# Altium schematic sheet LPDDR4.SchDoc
size D; SheetNumber: 9; SheetTotal: 9
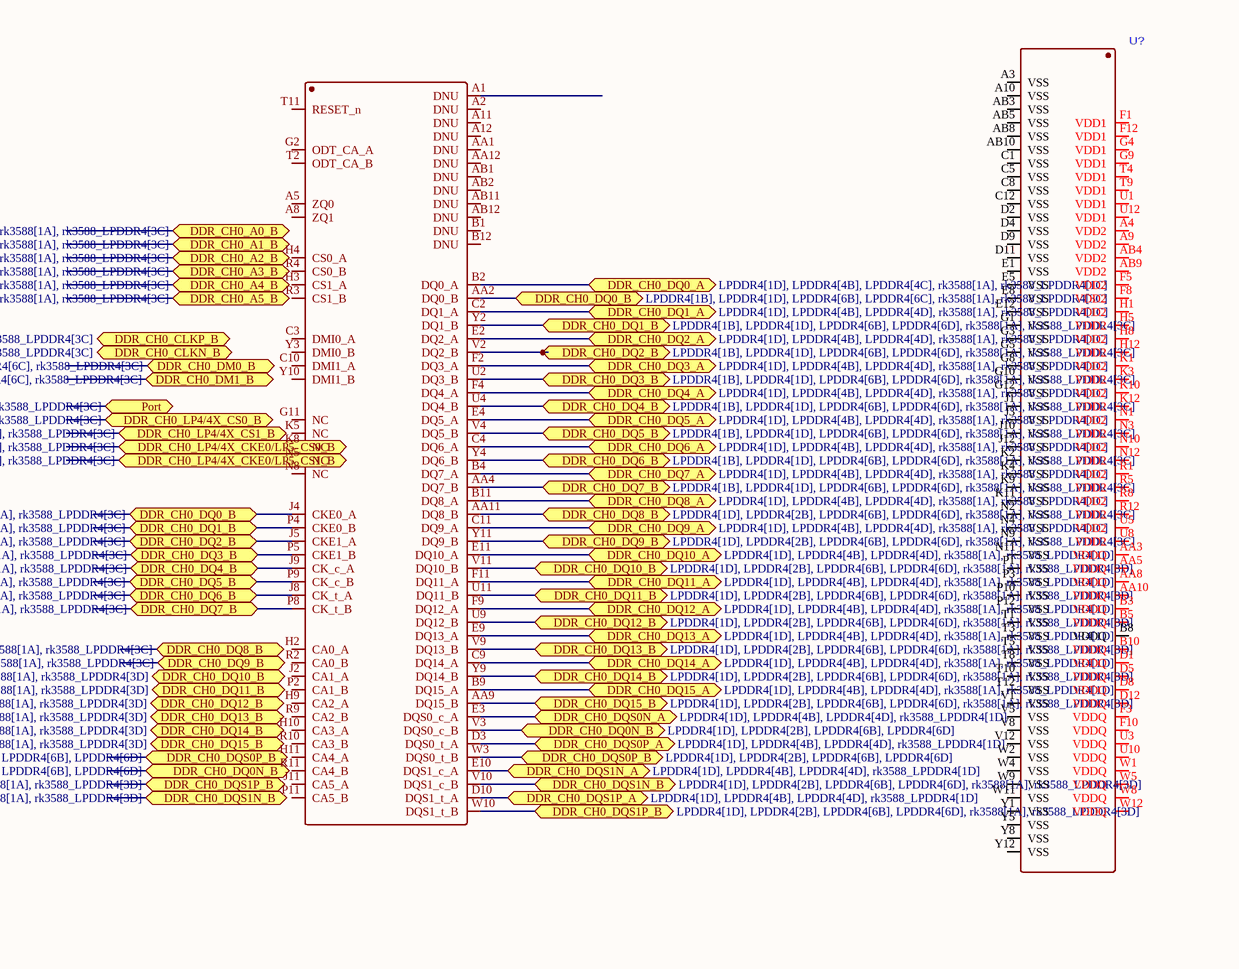
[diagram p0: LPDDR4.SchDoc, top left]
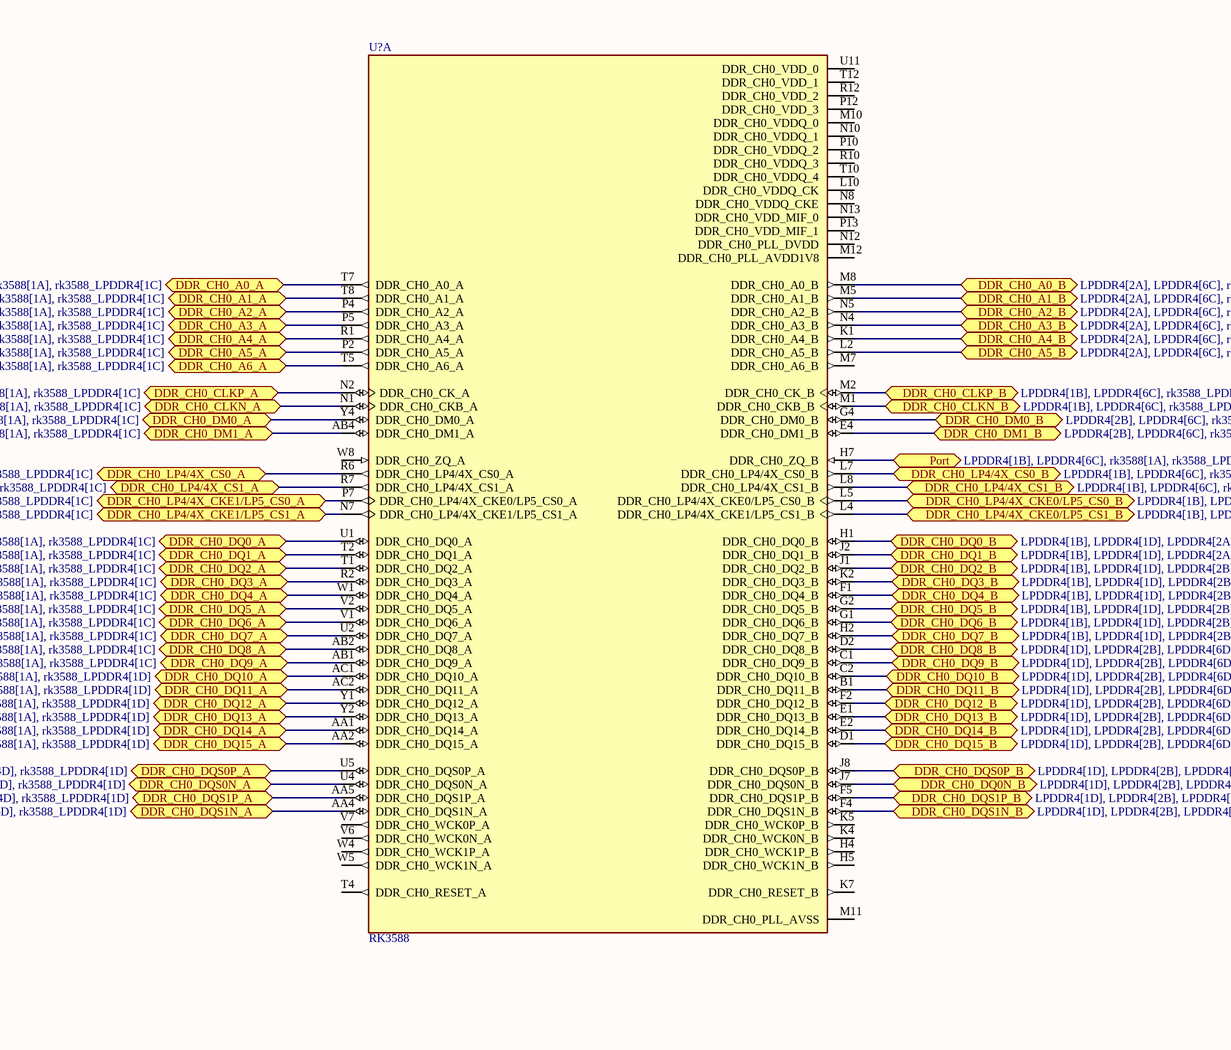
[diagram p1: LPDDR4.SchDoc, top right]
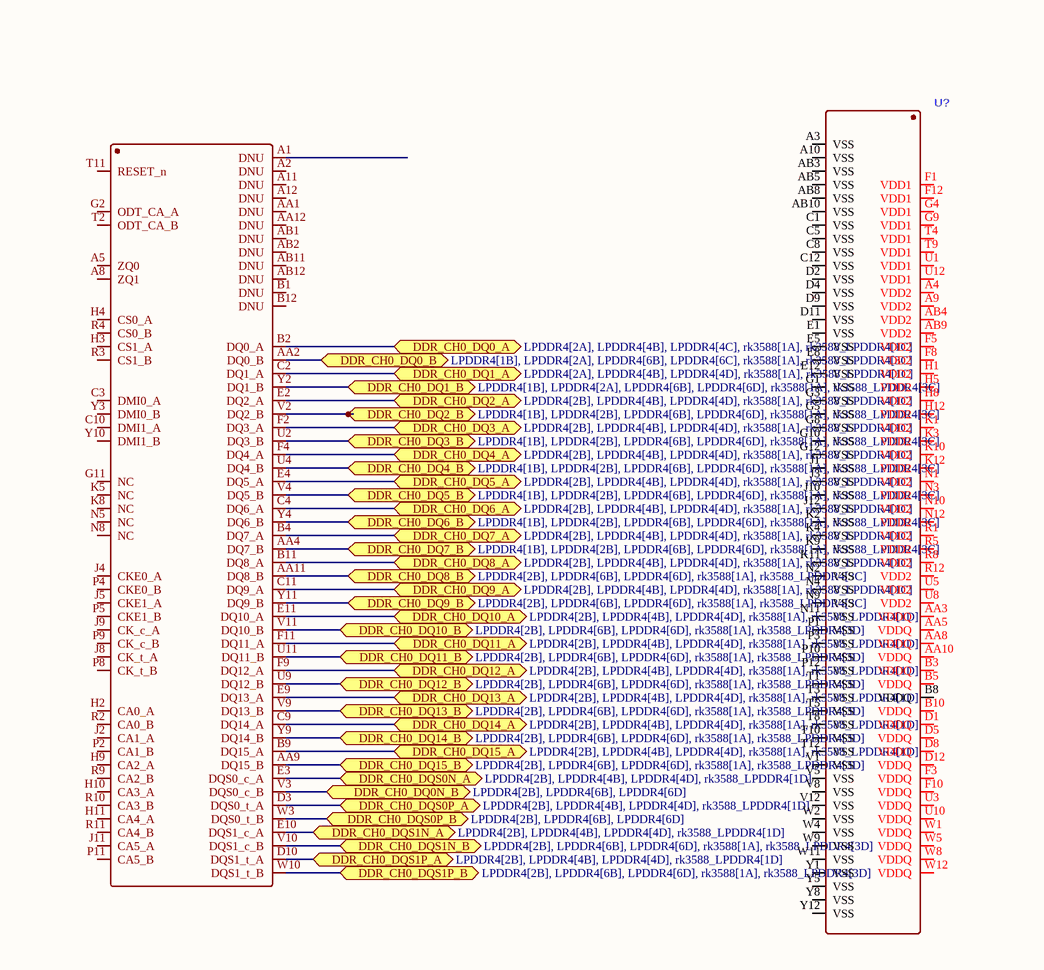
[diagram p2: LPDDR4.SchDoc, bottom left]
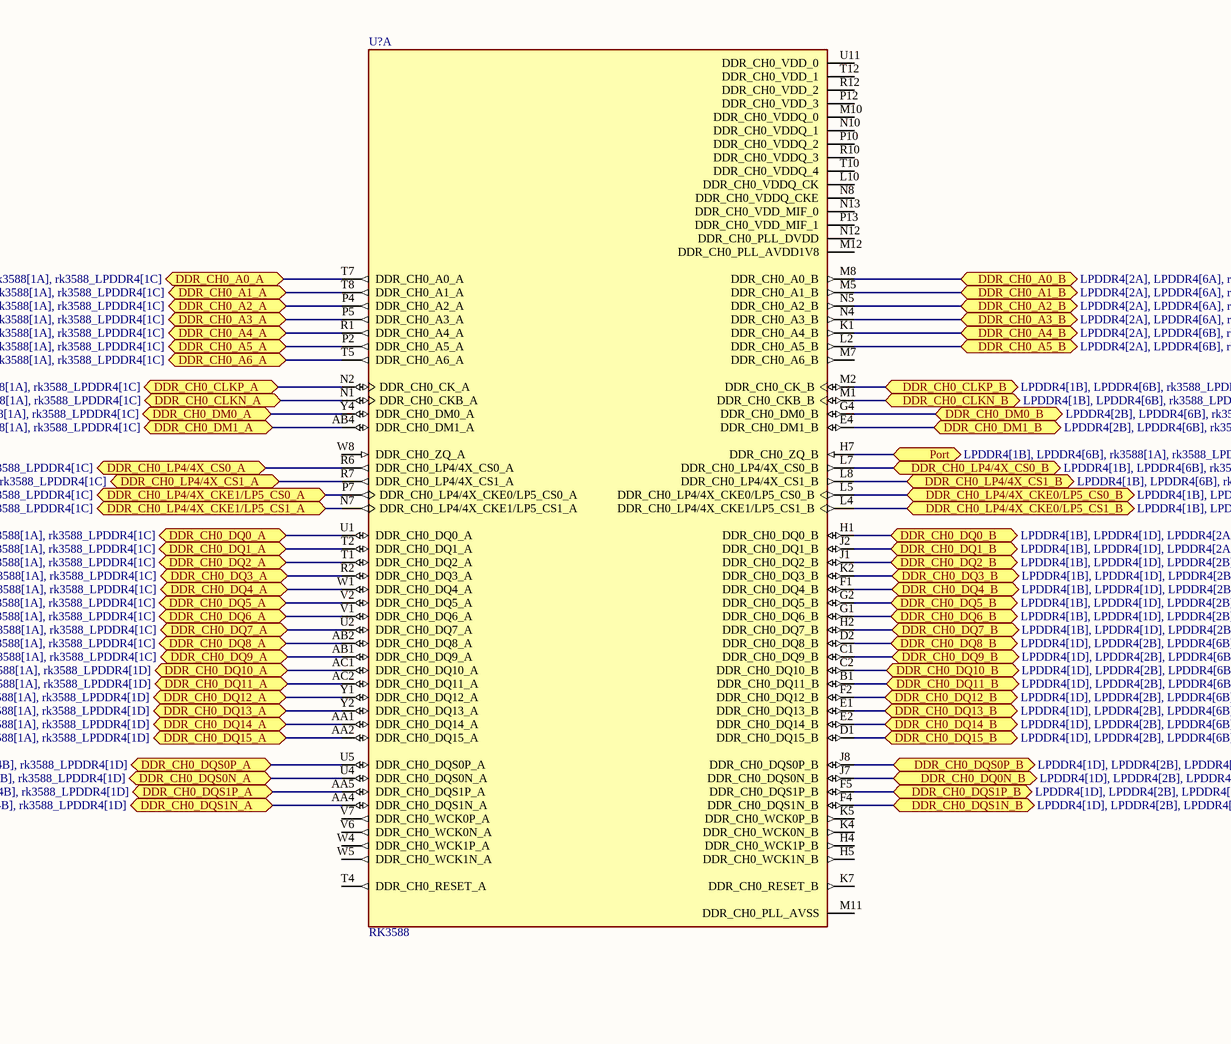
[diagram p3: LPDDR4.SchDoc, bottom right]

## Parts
(Parts that share a designator on the sheet are numbered #1, #2 ... from top to bottom, then left to right.)
U?#1  (no value)  [WFBGA-200_L14.5-W10.0-BL_MT53D512M32D2DS]
U?#2  RK3588  [BGA1088C65P34X34_2300X2300X204N]  (part A of 30)
U?#3  RK3588  [BGA1088C65P34X34_2300X2300X204N]  (part A of 30)
U?#4  (no value)  [WFBGA-200_L14.5-W10.0-BL_MT53D512M32D2DS]

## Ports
DDR_CH0_A0_A (bidir, see LPDDR4[4A], rk3588[1A], rk3588_LPDDR4[1C]), DDR_CH0_A0_A (bidir, see LPDDR4[4C], rk3588[1A], rk3588_LPDDR4[1C]), DDR_CH0_A0_B (bidir, see LPDDR4[2A], LPDDR4[6A], rk3588[1A], rk3588_LPDDR4[3C]), DDR_CH0_A0_B (bidir, see LPDDR4[2A], LPDDR4[6C], rk3588[1A], rk3588_LPDDR4[3C]), DDR_CH0_A0_B (bidir, see LPDDR4[6A], LPDDR4[6C], rk3588[1A], rk3588_LPDDR4[3C]), DDR_CH0_A1_A (bidir, see LPDDR4[4A], rk3588[1A], rk3588_LPDDR4[1C]), DDR_CH0_A1_A (bidir, see LPDDR4[4C], rk3588[1A], rk3588_LPDDR4[1C]), DDR_CH0_A1_B (bidir, see LPDDR4[2A], LPDDR4[6A], rk3588[1A], rk3588_LPDDR4[3C]), DDR_CH0_A1_B (bidir, see LPDDR4[2A], LPDDR4[6C], rk3588[1A], rk3588_LPDDR4[3C]), DDR_CH0_A1_B (bidir, see LPDDR4[6A], LPDDR4[6C], rk3588[1A], rk3588_LPDDR4[3C]), DDR_CH0_A2_A (bidir, see LPDDR4[4A], rk3588[1A], rk3588_LPDDR4[1C]), DDR_CH0_A2_A (bidir, see LPDDR4[4C], rk3588[1A], rk3588_LPDDR4[1C]), DDR_CH0_A2_B (bidir, see LPDDR4[2A], LPDDR4[6A], rk3588[1A], rk3588_LPDDR4[3C]), DDR_CH0_A2_B (bidir, see LPDDR4[2A], LPDDR4[6C], rk3588[1A], rk3588_LPDDR4[3C]), DDR_CH0_A2_B (bidir, see LPDDR4[6A], LPDDR4[6C], rk3588[1A], rk3588_LPDDR4[3C]), DDR_CH0_A3_A (bidir, see LPDDR4[4A], rk3588[1A], rk3588_LPDDR4[1C]), DDR_CH0_A3_A (bidir, see LPDDR4[4C], rk3588[1A], rk3588_LPDDR4[1C]), DDR_CH0_A3_B (bidir, see LPDDR4[2A], LPDDR4[6A], rk3588[1A], rk3588_LPDDR4[3C]), DDR_CH0_A3_B (bidir, see LPDDR4[2A], LPDDR4[6C], rk3588[1A], rk3588_LPDDR4[3C]), DDR_CH0_A3_B (bidir, see LPDDR4[6A], LPDDR4[6C], rk3588[1A], rk3588_LPDDR4[3C]), DDR_CH0_A4_A (bidir, see LPDDR4[4B], rk3588[1A], rk3588_LPDDR4[1C]), DDR_CH0_A4_A (bidir, see LPDDR4[4C], rk3588[1A], rk3588_LPDDR4[1C]), DDR_CH0_A4_B (bidir, see LPDDR4[2A], LPDDR4[6B], rk3588[1A], rk3588_LPDDR4[3C]), DDR_CH0_A4_B (bidir, see LPDDR4[2A], LPDDR4[6C], rk3588[1A], rk3588_LPDDR4[3C]), DDR_CH0_A4_B (bidir, see LPDDR4[6B], LPDDR4[6C], rk3588[1A], rk3588_LPDDR4[3C]), DDR_CH0_A5_A (bidir, see LPDDR4[4B], rk3588[1A], rk3588_LPDDR4[1C]), DDR_CH0_A5_A (bidir, see LPDDR4[4C], rk3588[1A], rk3588_LPDDR4[1C]), DDR_CH0_A5_B (bidir, see LPDDR4[2A], LPDDR4[6B], rk3588[1A], rk3588_LPDDR4[3C]), DDR_CH0_A5_B (bidir, see LPDDR4[2A], LPDDR4[6C], rk3588[1A], rk3588_LPDDR4[3C]), DDR_CH0_A5_B (bidir, see LPDDR4[6B], LPDDR4[6C], rk3588[1A], rk3588_LPDDR4[3C]), DDR_CH0_A6_A (bidir, see LPDDR4[4B], rk3588[1A], rk3588_LPDDR4[1C]), DDR_CH0_A6_A (bidir, see LPDDR4[4C], rk3588[1A], rk3588_LPDDR4[1C]), DDR_CH0_CLKN_A (bidir, see LPDDR4[4B], rk3588[1A], rk3588_LPDDR4[1C]), DDR_CH0_CLKN_A (bidir, see LPDDR4[4C], rk3588[1A], rk3588_LPDDR4[1C]), DDR_CH0_CLKN_B (bidir, see LPDDR4[1B], LPDDR4[6B], rk3588_LPDDR4[3C]), DDR_CH0_CLKN_B (bidir, see LPDDR4[1B], LPDDR4[6C], rk3588_LPDDR4[3C]), DDR_CH0_CLKN_B (bidir, see LPDDR4[6B], LPDDR4[6C], rk3588_LPDDR4[3C]), DDR_CH0_CLKP_A (bidir, see LPDDR4[4B], rk3588[1A], rk3588_LPDDR4[1C]), DDR_CH0_CLKP_A (bidir, see LPDDR4[4C], rk3588[1A], rk3588_LPDDR4[1C]), DDR_CH0_CLKP_B (bidir, see LPDDR4[1B], LPDDR4[6B], rk3588_LPDDR4[3C]), DDR_CH0_CLKP_B (bidir, see LPDDR4[1B], LPDDR4[6C], rk3588_LPDDR4[3C]), DDR_CH0_CLKP_B (bidir, see LPDDR4[6B], LPDDR4[6C], rk3588_LPDDR4[3C]), DDR_CH0_DM0_A (bidir, see LPDDR4[4B], rk3588[1A], rk3588_LPDDR4[1C]), DDR_CH0_DM0_A (bidir, see LPDDR4[4C], rk3588[1A], rk3588_LPDDR4[1C]), DDR_CH0_DM0_B (bidir, see LPDDR4[2B], LPDDR4[6B], rk3588_LPDDR4[3C]), DDR_CH0_DM0_B (bidir, see LPDDR4[2B], LPDDR4[6C], rk3588_LPDDR4[3C]), DDR_CH0_DM0_B (bidir, see LPDDR4[6B], LPDDR4[6C], rk3588_LPDDR4[3C]), DDR_CH0_DM1_A (bidir, see LPDDR4[4B], rk3588[1A], rk3588_LPDDR4[1C]), DDR_CH0_DM1_A (bidir, see LPDDR4[4C], rk3588[1A], rk3588_LPDDR4[1C]), DDR_CH0_DM1_B (bidir, see LPDDR4[2B], LPDDR4[6B], rk3588_LPDDR4[3C]), DDR_CH0_DM1_B (bidir, see LPDDR4[2B], LPDDR4[6C], rk3588_LPDDR4[3C]), DDR_CH0_DM1_B (bidir, see LPDDR4[6B], LPDDR4[6C], rk3588_LPDDR4[3C]), DDR_CH0_DQ0_A (bidir, see LPDDR4[1D], LPDDR4[2A], LPDDR4[4B], rk3588[1A], rk3588_LPDDR4[1C]), DDR_CH0_DQ0_A (bidir, see LPDDR4[1D], LPDDR4[2A], LPDDR4[4C], rk3588[1A], rk3588_LPDDR4[1C]), DDR_CH0_DQ0_A (bidir, see LPDDR4[1D], LPDDR4[4B], LPDDR4[4C], rk3588[1A], rk3588_LPDDR4[1C]), DDR_CH0_DQ0_A (bidir, see LPDDR4[2A], LPDDR4[4B], LPDDR4[4C], rk3588[1A], rk3588_LPDDR4[1C]), DDR_CH0_DQ0_B (bidir, see LPDDR4[1B], LPDDR4[1D], LPDDR4[2A], LPDDR4[6B], rk3588[1A], rk3588_LPDDR4[3C]), DDR_CH0_DQ0_B (bidir, see LPDDR4[1B], LPDDR4[1D], LPDDR4[2A], LPDDR4[6C], rk3588[1A], rk3588_LPDDR4[3C]), DDR_CH0_DQ0_B (bidir, see LPDDR4[1B], LPDDR4[1D], LPDDR4[6B], LPDDR4[6C], rk3588[1A], rk3588_LPDDR4[3C]), DDR_CH0_DQ0_B (bidir, see LPDDR4[1B], LPDDR4[2A], LPDDR4[6B], LPDDR4[6C], rk3588[1A], rk3588_LPDDR4[3C]), DDR_CH0_DQ0_B (bidir, see LPDDR4[1D], LPDDR4[2A], LPDDR4[6B], LPDDR4[6C], rk3588[1A], rk3588_LPDDR4[3C]), DDR_CH0_DQ0N_B (bidir, see LPDDR4[1D], LPDDR4[2B], LPDDR4[6B]), DDR_CH0_DQ0N_B (bidir, see LPDDR4[1D], LPDDR4[2B], LPDDR4[6B], LPDDR4[6D]), DDR_CH0_DQ0N_B (bidir, see LPDDR4[1D], LPDDR4[2B], LPDDR4[6D]), DDR_CH0_DQ0N_B (bidir, see LPDDR4[2B], LPDDR4[6B], LPDDR4[6D]), DDR_CH0_DQ1_A (bidir, see LPDDR4[1D], LPDDR4[2A], LPDDR4[4B], rk3588[1A], rk3588_LPDDR4[1C]), DDR_CH0_DQ1_A (bidir, see LPDDR4[1D], LPDDR4[2A], LPDDR4[4D], rk3588[1A], rk3588_LPDDR4[1C]), DDR_CH0_DQ1_A (bidir, see LPDDR4[1D], LPDDR4[4B], LPDDR4[4D], rk3588[1A], rk3588_LPDDR4[1C]), DDR_CH0_DQ1_A (bidir, see LPDDR4[2A], LPDDR4[4B], LPDDR4[4D], rk3588[1A], rk3588_LPDDR4[1C]), DDR_CH0_DQ1_B (bidir, see LPDDR4[1B], LPDDR4[1D], LPDDR4[2A], LPDDR4[6B], rk3588[1A], rk3588_LPDDR4[3C]), DDR_CH0_DQ1_B (bidir, see LPDDR4[1B], LPDDR4[1D], LPDDR4[2A], LPDDR4[6D], rk3588[1A], rk3588_LPDDR4[3C]), DDR_CH0_DQ1_B (bidir, see LPDDR4[1B], LPDDR4[1D], LPDDR4[6B], LPDDR4[6D], rk3588[1A], rk3588_LPDDR4[3C]), DDR_CH0_DQ1_B (bidir, see LPDDR4[1B], LPDDR4[2A], LPDDR4[6B], LPDDR4[6D], rk3588[1A], rk3588_LPDDR4[3C]), DDR_CH0_DQ1_B (bidir, see LPDDR4[1D], LPDDR4[2A], LPDDR4[6B], LPDDR4[6D], rk3588[1A], rk3588_LPDDR4[3C]), DDR_CH0_DQ2_A (bidir, see LPDDR4[1D], LPDDR4[2B], LPDDR4[4B], rk3588[1A], rk3588_LPDDR4[1C]), DDR_CH0_DQ2_A (bidir, see LPDDR4[1D], LPDDR4[2B], LPDDR4[4D], rk3588[1A], rk3588_LPDDR4[1C]), DDR_CH0_DQ2_A (bidir, see LPDDR4[1D], LPDDR4[4B], LPDDR4[4D], rk3588[1A], rk3588_LPDDR4[1C]), DDR_CH0_DQ2_A (bidir, see LPDDR4[2B], LPDDR4[4B], LPDDR4[4D], rk3588[1A], rk3588_LPDDR4[1C]), DDR_CH0_DQ2_B (bidir, see LPDDR4[1B], LPDDR4[1D], LPDDR4[2B], LPDDR4[6B], rk3588[1A], rk3588_LPDDR4[3C]), DDR_CH0_DQ2_B (bidir, see LPDDR4[1B], LPDDR4[1D], LPDDR4[2B], LPDDR4[6D], rk3588[1A], rk3588_LPDDR4[3C]), DDR_CH0_DQ2_B (bidir, see LPDDR4[1B], LPDDR4[1D], LPDDR4[6B], LPDDR4[6D], rk3588[1A], rk3588_LPDDR4[3C]), DDR_CH0_DQ2_B (bidir, see LPDDR4[1B], LPDDR4[2B], LPDDR4[6B], LPDDR4[6D], rk3588[1A], rk3588_LPDDR4[3C]), DDR_CH0_DQ2_B (bidir, see LPDDR4[1D], LPDDR4[2B], LPDDR4[6B], LPDDR4[6D], rk3588[1A], rk3588_LPDDR4[3C]), DDR_CH0_DQ3_A (bidir, see LPDDR4[1D], LPDDR4[2B], LPDDR4[4B], rk3588[1A], rk3588_LPDDR4[1C]), DDR_CH0_DQ3_A (bidir, see LPDDR4[1D], LPDDR4[2B], LPDDR4[4D], rk3588[1A], rk3588_LPDDR4[1C]), DDR_CH0_DQ3_A (bidir, see LPDDR4[1D], LPDDR4[4B], LPDDR4[4D], rk3588[1A], rk3588_LPDDR4[1C]), DDR_CH0_DQ3_A (bidir, see LPDDR4[2B], LPDDR4[4B], LPDDR4[4D], rk3588[1A], rk3588_LPDDR4[1C]), DDR_CH0_DQ3_B (bidir, see LPDDR4[1B], LPDDR4[1D], LPDDR4[2B], LPDDR4[6B], rk3588[1A], rk3588_LPDDR4[3C]), DDR_CH0_DQ3_B (bidir, see LPDDR4[1B], LPDDR4[1D], LPDDR4[2B], LPDDR4[6D], rk3588[1A], rk3588_LPDDR4[3C]), DDR_CH0_DQ3_B (bidir, see LPDDR4[1B], LPDDR4[1D], LPDDR4[6B], LPDDR4[6D], rk3588[1A], rk3588_LPDDR4[3C]), DDR_CH0_DQ3_B (bidir, see LPDDR4[1B], LPDDR4[2B], LPDDR4[6B], LPDDR4[6D], rk3588[1A], rk3588_LPDDR4[3C]), DDR_CH0_DQ3_B (bidir, see LPDDR4[1D], LPDDR4[2B], LPDDR4[6B], LPDDR4[6D], rk3588[1A], rk3588_LPDDR4[3C]), DDR_CH0_DQ4_A (bidir, see LPDDR4[1D], LPDDR4[2B], LPDDR4[4B], rk3588[1A], rk3588_LPDDR4[1C]), DDR_CH0_DQ4_A (bidir, see LPDDR4[1D], LPDDR4[2B], LPDDR4[4D], rk3588[1A], rk3588_LPDDR4[1C]), DDR_CH0_DQ4_A (bidir, see LPDDR4[1D], LPDDR4[4B], LPDDR4[4D], rk3588[1A], rk3588_LPDDR4[1C]), DDR_CH0_DQ4_A (bidir, see LPDDR4[2B], LPDDR4[4B], LPDDR4[4D], rk3588[1A], rk3588_LPDDR4[1C]), DDR_CH0_DQ4_B (bidir, see LPDDR4[1B], LPDDR4[1D], LPDDR4[2B], LPDDR4[6B], rk3588[1A], rk3588_LPDDR4[3C]), DDR_CH0_DQ4_B (bidir, see LPDDR4[1B], LPDDR4[1D], LPDDR4[2B], LPDDR4[6D], rk3588[1A], rk3588_LPDDR4[3C]), DDR_CH0_DQ4_B (bidir, see LPDDR4[1B], LPDDR4[1D], LPDDR4[6B], LPDDR4[6D], rk3588[1A], rk3588_LPDDR4[3C]), DDR_CH0_DQ4_B (bidir, see LPDDR4[1B], LPDDR4[2B], LPDDR4[6B], LPDDR4[6D], rk3588[1A], rk3588_LPDDR4[3C]), DDR_CH0_DQ4_B (bidir, see LPDDR4[1D], LPDDR4[2B], LPDDR4[6B], LPDDR4[6D], rk3588[1A], rk3588_LPDDR4[3C]), DDR_CH0_DQ5_A (bidir, see LPDDR4[1D], LPDDR4[2B], LPDDR4[4B], rk3588[1A], rk3588_LPDDR4[1C]), DDR_CH0_DQ5_A (bidir, see LPDDR4[1D], LPDDR4[2B], LPDDR4[4D], rk3588[1A], rk3588_LPDDR4[1C]), DDR_CH0_DQ5_A (bidir, see LPDDR4[1D], LPDDR4[4B], LPDDR4[4D], rk3588[1A], rk3588_LPDDR4[1C]), DDR_CH0_DQ5_A (bidir, see LPDDR4[2B], LPDDR4[4B], LPDDR4[4D], rk3588[1A], rk3588_LPDDR4[1C]), DDR_CH0_DQ5_B (bidir, see LPDDR4[1B], LPDDR4[1D], LPDDR4[2B], LPDDR4[6B], rk3588[1A], rk3588_LPDDR4[3C]), DDR_CH0_DQ5_B (bidir, see LPDDR4[1B], LPDDR4[1D], LPDDR4[2B], LPDDR4[6D], rk3588[1A], rk3588_LPDDR4[3C]), DDR_CH0_DQ5_B (bidir, see LPDDR4[1B], LPDDR4[1D], LPDDR4[6B], LPDDR4[6D], rk3588[1A], rk3588_LPDDR4[3C]), DDR_CH0_DQ5_B (bidir, see LPDDR4[1B], LPDDR4[2B], LPDDR4[6B], LPDDR4[6D], rk3588[1A], rk3588_LPDDR4[3C]), DDR_CH0_DQ5_B (bidir, see LPDDR4[1D], LPDDR4[2B], LPDDR4[6B], LPDDR4[6D], rk3588[1A], rk3588_LPDDR4[3C]), DDR_CH0_DQ6_A (bidir, see LPDDR4[1D], LPDDR4[2B], LPDDR4[4B], rk3588[1A], rk3588_LPDDR4[1C]), DDR_CH0_DQ6_A (bidir, see LPDDR4[1D], LPDDR4[2B], LPDDR4[4D], rk3588[1A], rk3588_LPDDR4[1C]), DDR_CH0_DQ6_A (bidir, see LPDDR4[1D], LPDDR4[4B], LPDDR4[4D], rk3588[1A], rk3588_LPDDR4[1C]), DDR_CH0_DQ6_A (bidir, see LPDDR4[2B], LPDDR4[4B], LPDDR4[4D], rk3588[1A], rk3588_LPDDR4[1C]), DDR_CH0_DQ6_B (bidir, see LPDDR4[1B], LPDDR4[1D], LPDDR4[2B], LPDDR4[6B], rk3588[1A], rk3588_LPDDR4[3C]), DDR_CH0_DQ6_B (bidir, see LPDDR4[1B], LPDDR4[1D], LPDDR4[2B], LPDDR4[6D], rk3588[1A], rk3588_LPDDR4[3C]), DDR_CH0_DQ6_B (bidir, see LPDDR4[1B], LPDDR4[1D], LPDDR4[6B], LPDDR4[6D], rk3588[1A], rk3588_LPDDR4[3C]), DDR_CH0_DQ6_B (bidir, see LPDDR4[1B], LPDDR4[2B], LPDDR4[6B], LPDDR4[6D], rk3588[1A], rk3588_LPDDR4[3C]), DDR_CH0_DQ6_B (bidir, see LPDDR4[1D], LPDDR4[2B], LPDDR4[6B], LPDDR4[6D], rk3588[1A], rk3588_LPDDR4[3C]), DDR_CH0_DQ7_A (bidir, see LPDDR4[1D], LPDDR4[2B], LPDDR4[4B], rk3588[1A], rk3588_LPDDR4[1C]), DDR_CH0_DQ7_A (bidir, see LPDDR4[1D], LPDDR4[2B], LPDDR4[4D], rk3588[1A], rk3588_LPDDR4[1C]), DDR_CH0_DQ7_A (bidir, see LPDDR4[1D], LPDDR4[4B], LPDDR4[4D], rk3588[1A], rk3588_LPDDR4[1C]), DDR_CH0_DQ7_A (bidir, see LPDDR4[2B], LPDDR4[4B], LPDDR4[4D], rk3588[1A], rk3588_LPDDR4[1C]), DDR_CH0_DQ7_B (bidir, see LPDDR4[1B], LPDDR4[1D], LPDDR4[2B], LPDDR4[6B], rk3588[1A], rk3588_LPDDR4[3C]), DDR_CH0_DQ7_B (bidir, see LPDDR4[1B], LPDDR4[1D], LPDDR4[2B], LPDDR4[6D], rk3588[1A], rk3588_LPDDR4[3C]), DDR_CH0_DQ7_B (bidir, see LPDDR4[1B], LPDDR4[1D], LPDDR4[6B], LPDDR4[6D], rk3588[1A], rk3588_LPDDR4[3C]), DDR_CH0_DQ7_B (bidir, see LPDDR4[1B], LPDDR4[2B], LPDDR4[6B], LPDDR4[6D], rk3588[1A], rk3588_LPDDR4[3C]), DDR_CH0_DQ7_B (bidir, see LPDDR4[1D], LPDDR4[2B], LPDDR4[6B], LPDDR4[6D], rk3588[1A], rk3588_LPDDR4[3C]), DDR_CH0_DQ8_A (bidir, see LPDDR4[1D], LPDDR4[2B], LPDDR4[4B], rk3588[1A], rk3588_LPDDR4[1C]), DDR_CH0_DQ8_A (bidir, see LPDDR4[1D], LPDDR4[2B], LPDDR4[4D], rk3588[1A], rk3588_LPDDR4[1C]), DDR_CH0_DQ8_A (bidir, see LPDDR4[1D], LPDDR4[4B], LPDDR4[4D], rk3588[1A], rk3588_LPDDR4[1C]), DDR_CH0_DQ8_A (bidir, see LPDDR4[2B], LPDDR4[4B], LPDDR4[4D], rk3588[1A], rk3588_LPDDR4[1C]), DDR_CH0_DQ8_B (bidir, see LPDDR4[1D], LPDDR4[2B], LPDDR4[6B], LPDDR4[6D], rk3588[1A], rk3588_LPDDR4[3C]), DDR_CH0_DQ8_B (bidir, see LPDDR4[1D], LPDDR4[2B], LPDDR4[6B], rk3588[1A], rk3588_LPDDR4[3C]), DDR_CH0_DQ8_B (bidir, see LPDDR4[1D], LPDDR4[2B], LPDDR4[6D], rk3588[1A], rk3588_LPDDR4[3C]), DDR_CH0_DQ8_B (bidir, see LPDDR4[2B], LPDDR4[6B], LPDDR4[6D], rk3588[1A], rk3588_LPDDR4[3C]), DDR_CH0_DQ9_A (bidir, see LPDDR4[1D], LPDDR4[2B], LPDDR4[4B], rk3588[1A], rk3588_LPDDR4[1C]), DDR_CH0_DQ9_A (bidir, see LPDDR4[1D], LPDDR4[2B], LPDDR4[4D], rk3588[1A], rk3588_LPDDR4[1C]), DDR_CH0_DQ9_A (bidir, see LPDDR4[1D], LPDDR4[4B], LPDDR4[4D], rk3588[1A], rk3588_LPDDR4[1C]), DDR_CH0_DQ9_A (bidir, see LPDDR4[2B], LPDDR4[4B], LPDDR4[4D], rk3588[1A], rk3588_LPDDR4[1C]), DDR_CH0_DQ9_B (bidir, see LPDDR4[1D], LPDDR4[2B], LPDDR4[6B], LPDDR4[6D], rk3588[1A], rk3588_LPDDR4[3C]), DDR_CH0_DQ9_B (bidir, see LPDDR4[1D], LPDDR4[2B], LPDDR4[6B], rk3588[1A], rk3588_LPDDR4[3C]), DDR_CH0_DQ9_B (bidir, see LPDDR4[1D], LPDDR4[2B], LPDDR4[6D], rk3588[1A], rk3588_LPDDR4[3C]), DDR_CH0_DQ9_B (bidir, see LPDDR4[2B], LPDDR4[6B], LPDDR4[6D], rk3588[1A], rk3588_LPDDR4[3C]), DDR_CH0_DQ10_A (bidir, see LPDDR4[1D], LPDDR4[2B], LPDDR4[4B], rk3588[1A], rk3588_LPDDR4[1D]), DDR_CH0_DQ10_A (bidir, see LPDDR4[1D], LPDDR4[2B], LPDDR4[4D], rk3588[1A], rk3588_LPDDR4[1D]), DDR_CH0_DQ10_A (bidir, see LPDDR4[1D], LPDDR4[4B], LPDDR4[4D], rk3588[1A], rk3588_LPDDR4[1D]), DDR_CH0_DQ10_A (bidir, see LPDDR4[2B], LPDDR4[4B], LPDDR4[4D], rk3588[1A], rk3588_LPDDR4[1D]), DDR_CH0_DQ10_B (bidir, see LPDDR4[1D], LPDDR4[2B], LPDDR4[6B], LPDDR4[6D], rk3588[1A], rk3588_LPDDR4[3D]), DDR_CH0_DQ10_B (bidir, see LPDDR4[1D], LPDDR4[2B], LPDDR4[6B], rk3588[1A], rk3588_LPDDR4[3D]), DDR_CH0_DQ10_B (bidir, see LPDDR4[1D], LPDDR4[2B], LPDDR4[6D], rk3588[1A], rk3588_LPDDR4[3D]), DDR_CH0_DQ10_B (bidir, see LPDDR4[2B], LPDDR4[6B], LPDDR4[6D], rk3588[1A], rk3588_LPDDR4[3D]), DDR_CH0_DQ11_A (bidir, see LPDDR4[1D], LPDDR4[2B], LPDDR4[4B], rk3588[1A], rk3588_LPDDR4[1D]), DDR_CH0_DQ11_A (bidir, see LPDDR4[1D], LPDDR4[2B], LPDDR4[4D], rk3588[1A], rk3588_LPDDR4[1D]), DDR_CH0_DQ11_A (bidir, see LPDDR4[1D], LPDDR4[4B], LPDDR4[4D], rk3588[1A], rk3588_LPDDR4[1D]), DDR_CH0_DQ11_A (bidir, see LPDDR4[2B], LPDDR4[4B], LPDDR4[4D], rk3588[1A], rk3588_LPDDR4[1D]), DDR_CH0_DQ11_B (bidir, see LPDDR4[1D], LPDDR4[2B], LPDDR4[6B], LPDDR4[6D], rk3588[1A], rk3588_LPDDR4[3D]), DDR_CH0_DQ11_B (bidir, see LPDDR4[1D], LPDDR4[2B], LPDDR4[6B], rk3588[1A], rk3588_LPDDR4[3D]), DDR_CH0_DQ11_B (bidir, see LPDDR4[1D], LPDDR4[2B], LPDDR4[6D], rk3588[1A], rk3588_LPDDR4[3D]), DDR_CH0_DQ11_B (bidir, see LPDDR4[2B], LPDDR4[6B], LPDDR4[6D], rk3588[1A], rk3588_LPDDR4[3D]), DDR_CH0_DQ12_A (bidir, see LPDDR4[1D], LPDDR4[2B], LPDDR4[4B], rk3588[1A], rk3588_LPDDR4[1D]), DDR_CH0_DQ12_A (bidir, see LPDDR4[1D], LPDDR4[2B], LPDDR4[4D], rk3588[1A], rk3588_LPDDR4[1D]), DDR_CH0_DQ12_A (bidir, see LPDDR4[1D], LPDDR4[4B], LPDDR4[4D], rk3588[1A], rk3588_LPDDR4[1D]), DDR_CH0_DQ12_A (bidir, see LPDDR4[2B], LPDDR4[4B], LPDDR4[4D], rk3588[1A], rk3588_LPDDR4[1D]), DDR_CH0_DQ12_B (bidir, see LPDDR4[1D], LPDDR4[2B], LPDDR4[6B], LPDDR4[6D], rk3588[1A], rk3588_LPDDR4[3D]), DDR_CH0_DQ12_B (bidir, see LPDDR4[1D], LPDDR4[2B], LPDDR4[6B], rk3588[1A], rk3588_LPDDR4[3D]), DDR_CH0_DQ12_B (bidir, see LPDDR4[1D], LPDDR4[2B], LPDDR4[6D], rk3588[1A], rk3588_LPDDR4[3D]), DDR_CH0_DQ12_B (bidir, see LPDDR4[2B], LPDDR4[6B], LPDDR4[6D], rk3588[1A], rk3588_LPDDR4[3D]), DDR_CH0_DQ13_A (bidir, see LPDDR4[1D], LPDDR4[2B], LPDDR4[4B], rk3588[1A], rk3588_LPDDR4[1D]), DDR_CH0_DQ13_A (bidir, see LPDDR4[1D], LPDDR4[2B], LPDDR4[4D], rk3588[1A], rk3588_LPDDR4[1D]), DDR_CH0_DQ13_A (bidir, see LPDDR4[1D], LPDDR4[4B], LPDDR4[4D], rk3588[1A], rk3588_LPDDR4[1D]), DDR_CH0_DQ13_A (bidir, see LPDDR4[2B], LPDDR4[4B], LPDDR4[4D], rk3588[1A], rk3588_LPDDR4[1D]), DDR_CH0_DQ13_B (bidir, see LPDDR4[1D], LPDDR4[2B], LPDDR4[6B], LPDDR4[6D], rk3588[1A], rk3588_LPDDR4[3D]), DDR_CH0_DQ13_B (bidir, see LPDDR4[1D], LPDDR4[2B], LPDDR4[6B], rk3588[1A], rk3588_LPDDR4[3D]), DDR_CH0_DQ13_B (bidir, see LPDDR4[1D], LPDDR4[2B], LPDDR4[6D], rk3588[1A], rk3588_LPDDR4[3D]), DDR_CH0_DQ13_B (bidir, see LPDDR4[2B], LPDDR4[6B], LPDDR4[6D], rk3588[1A], rk3588_LPDDR4[3D]), DDR_CH0_DQ14_A (bidir, see LPDDR4[1D], LPDDR4[2B], LPDDR4[4B], rk3588[1A], rk3588_LPDDR4[1D]), DDR_CH0_DQ14_A (bidir, see LPDDR4[1D], LPDDR4[2B], LPDDR4[4D], rk3588[1A], rk3588_LPDDR4[1D]), DDR_CH0_DQ14_A (bidir, see LPDDR4[1D], LPDDR4[4B], LPDDR4[4D], rk3588[1A], rk3588_LPDDR4[1D]), DDR_CH0_DQ14_A (bidir, see LPDDR4[2B], LPDDR4[4B], LPDDR4[4D], rk3588[1A], rk3588_LPDDR4[1D]), DDR_CH0_DQ14_B (bidir, see LPDDR4[1D], LPDDR4[2B], LPDDR4[6B], LPDDR4[6D], rk3588[1A], rk3588_LPDDR4[3D]), DDR_CH0_DQ14_B (bidir, see LPDDR4[1D], LPDDR4[2B], LPDDR4[6B], rk3588[1A], rk3588_LPDDR4[3D]), DDR_CH0_DQ14_B (bidir, see LPDDR4[1D], LPDDR4[2B], LPDDR4[6D], rk3588[1A], rk3588_LPDDR4[3D]), DDR_CH0_DQ14_B (bidir, see LPDDR4[2B], LPDDR4[6B], LPDDR4[6D], rk3588[1A], rk3588_LPDDR4[3D]), DDR_CH0_DQ15_A (bidir, see LPDDR4[1D], LPDDR4[2B], LPDDR4[4B], rk3588[1A], rk3588_LPDDR4[1D]), DDR_CH0_DQ15_A (bidir, see LPDDR4[1D], LPDDR4[2B], LPDDR4[4D], rk3588[1A], rk3588_LPDDR4[1D]), DDR_CH0_DQ15_A (bidir, see LPDDR4[1D], LPDDR4[4B], LPDDR4[4D], rk3588[1A], rk3588_LPDDR4[1D]), DDR_CH0_DQ15_A (bidir, see LPDDR4[2B], LPDDR4[4B], LPDDR4[4D], rk3588[1A], rk3588_LPDDR4[1D]), DDR_CH0_DQ15_B (bidir, see LPDDR4[1D], LPDDR4[2B], LPDDR4[6B], LPDDR4[6D], rk3588[1A], rk3588_LPDDR4[3D]), DDR_CH0_DQ15_B (bidir, see LPDDR4[1D], LPDDR4[2B], LPDDR4[6B], rk3588[1A], rk3588_LPDDR4[3D]), DDR_CH0_DQ15_B (bidir, see LPDDR4[1D], LPDDR4[2B], LPDDR4[6D], rk3588[1A], rk3588_LPDDR4[3D]), DDR_CH0_DQ15_B (bidir, see LPDDR4[2B], LPDDR4[6B], LPDDR4[6D], rk3588[1A], rk3588_LPDDR4[3D]), DDR_CH0_DQS0N_A (bidir, see LPDDR4[1D], LPDDR4[2B], LPDDR4[4B], rk3588_LPDDR4[1D]), DDR_CH0_DQS0N_A (bidir, see LPDDR4[1D], LPDDR4[2B], LPDDR4[4D], rk3588_LPDDR4[1D]), DDR_CH0_DQS0N_A (bidir, see LPDDR4[1D], LPDDR4[4B], LPDDR4[4D], rk3588_LPDDR4[1D]), DDR_CH0_DQS0N_A (bidir, see LPDDR4[2B], LPDDR4[4B], LPDDR4[4D], rk3588_LPDDR4[1D]), DDR_CH0_DQS0P_A (bidir, see LPDDR4[1D], LPDDR4[2B], LPDDR4[4B], rk3588_LPDDR4[1D]), DDR_CH0_DQS0P_A (bidir, see LPDDR4[1D], LPDDR4[2B], LPDDR4[4D], rk3588_LPDDR4[1D]), DDR_CH0_DQS0P_A (bidir, see LPDDR4[1D], LPDDR4[4B], LPDDR4[4D], rk3588_LPDDR4[1D]), DDR_CH0_DQS0P_A (bidir, see LPDDR4[2B], LPDDR4[4B], LPDDR4[4D], rk3588_LPDDR4[1D]), DDR_CH0_DQS0P_B (bidir, see LPDDR4[1D], LPDDR4[2B], LPDDR4[6B]), DDR_CH0_DQS0P_B (bidir, see LPDDR4[1D], LPDDR4[2B], LPDDR4[6B], LPDDR4[6D]), DDR_CH0_DQS0P_B (bidir, see LPDDR4[1D], LPDDR4[2B], LPDDR4[6D]), DDR_CH0_DQS0P_B (bidir, see LPDDR4[2B], LPDDR4[6B], LPDDR4[6D]), DDR_CH0_DQS1N_A (bidir, see LPDDR4[1D], LPDDR4[2B], LPDDR4[4B], rk3588_LPDDR4[1D]), DDR_CH0_DQS1N_A (bidir, see LPDDR4[1D], LPDDR4[2B], LPDDR4[4D], rk3588_LPDDR4[1D]), DDR_CH0_DQS1N_A (bidir, see LPDDR4[1D], LPDDR4[4B], LPDDR4[4D], rk3588_LPDDR4[1D]), DDR_CH0_DQS1N_A (bidir, see LPDDR4[2B], LPDDR4[4B], LPDDR4[4D], rk3588_LPDDR4[1D]), DDR_CH0_DQS1N_B (bidir, see LPDDR4[1D], LPDDR4[2B], LPDDR4[6B], LPDDR4[6D], rk3588[1A], rk3588_LPDDR4[3D]), DDR_CH0_DQS1N_B (bidir, see LPDDR4[1D], LPDDR4[2B], LPDDR4[6B], rk3588[1A], rk3588_LPDDR4[3D]), DDR_CH0_DQS1N_B (bidir, see LPDDR4[1D], LPDDR4[2B], LPDDR4[6D], rk3588[1A], rk3588_LPDDR4[3D]), DDR_CH0_DQS1N_B (bidir, see LPDDR4[2B], LPDDR4[6B], LPDDR4[6D], rk3588[1A], rk3588_LPDDR4[3D]), DDR_CH0_DQS1P_A (bidir, see LPDDR4[1D], LPDDR4[2B], LPDDR4[4B], rk3588_LPDDR4[1D]), DDR_CH0_DQS1P_A (bidir, see LPDDR4[1D], LPDDR4[2B], LPDDR4[4D], rk3588_LPDDR4[1D]), DDR_CH0_DQS1P_A (bidir, see LPDDR4[1D], LPDDR4[4B], LPDDR4[4D], rk3588_LPDDR4[1D]), DDR_CH0_DQS1P_A (bidir, see LPDDR4[2B], LPDDR4[4B], LPDDR4[4D], rk3588_LPDDR4[1D]), DDR_CH0_DQS1P_B (bidir, see LPDDR4[1D], LPDDR4[2B], LPDDR4[6B], LPDDR4[6D], rk3588[1A], rk3588_LPDDR4[3D]), DDR_CH0_DQS1P_B (bidir, see LPDDR4[1D], LPDDR4[2B], LPDDR4[6B], rk3588[1A], rk3588_LPDDR4[3D]), DDR_CH0_DQS1P_B (bidir, see LPDDR4[1D], LPDDR4[2B], LPDDR4[6D], rk3588[1A], rk3588_LPDDR4[3D]), DDR_CH0_DQS1P_B (bidir, see LPDDR4[2B], LPDDR4[6B], LPDDR4[6D], rk3588[1A], rk3588_LPDDR4[3D]), DDR_CH0_LP4/4X_CKE0/LP5_CS0_B (bidir, see LPDDR4[1B], LPDDR4[6B], rk3588[1A], rk3588_LPDDR4[3C]), DDR_CH0_LP4/4X_CKE0/LP5_CS0_B (bidir, see LPDDR4[1B], LPDDR4[6C], rk3588[1A], rk3588_LPDDR4[3C]), DDR_CH0_LP4/4X_CKE0/LP5_CS0_B (bidir, see LPDDR4[6B], LPDDR4[6C], rk3588[1A], rk3588_LPDDR4[3C]), DDR_CH0_LP4/4X_CKE0/LP5_CS1_B (bidir, see LPDDR4[1B], LPDDR4[6B], rk3588[1A], rk3588_LPDDR4[3C]), DDR_CH0_LP4/4X_CKE0/LP5_CS1_B (bidir, see LPDDR4[1B], LPDDR4[6C], rk3588[1A], rk3588_LPDDR4[3C]), DDR_CH0_LP4/4X_CKE0/LP5_CS1_B (bidir, see LPDDR4[6B], LPDDR4[6C], rk3588[1A], rk3588_LPDDR4[3C]), DDR_CH0_LP4/4X_CKE1/LP5_CS0_A (bidir, see LPDDR4[4B], rk3588[1A], rk3588_LPDDR4[1C]), DDR_CH0_LP4/4X_CKE1/LP5_CS0_A (bidir, see LPDDR4[4C], rk3588[1A], rk3588_LPDDR4[1C]), DDR_CH0_LP4/4X_CKE1/LP5_CS1_A (bidir, see LPDDR4[4B], rk3588[1A], rk3588_LPDDR4[1C]), DDR_CH0_LP4/4X_CKE1/LP5_CS1_A (bidir, see LPDDR4[4C], rk3588[1A], rk3588_LPDDR4[1C]), DDR_CH0_LP4/4X_CS0_A (bidir, see LPDDR4[4B], rk3588[1A], rk3588_LPDDR4[1C]), DDR_CH0_LP4/4X_CS0_A (bidir, see LPDDR4[4C], rk3588[1A], rk3588_LPDDR4[1C]), DDR_CH0_LP4/4X_CS0_B (bidir, see LPDDR4[1B], LPDDR4[6B], rk3588[1A], rk3588_LPDDR4[3C]), DDR_CH0_LP4/4X_CS0_B (bidir, see LPDDR4[1B], LPDDR4[6C], rk3588[1A], rk3588_LPDDR4[3C]), DDR_CH0_LP4/4X_CS0_B (bidir, see LPDDR4[6B], LPDDR4[6C], rk3588[1A], rk3588_LPDDR4[3C]), DDR_CH0_LP4/4X_CS1_A (bidir, see LPDDR4[4B], rk3588[1A], rk3588_LPDDR4[1C]), DDR_CH0_LP4/4X_CS1_A (bidir, see LPDDR4[4C], rk3588[1A], rk3588_LPDDR4[1C]), DDR_CH0_LP4/4X_CS1_B (bidir, see LPDDR4[1B], LPDDR4[6B], rk3588[1A], rk3588_LPDDR4[3C]), DDR_CH0_LP4/4X_CS1_B (bidir, see LPDDR4[1B], LPDDR4[6C], rk3588[1A], rk3588_LPDDR4[3C]), DDR_CH0_LP4/4X_CS1_B (bidir, see LPDDR4[6B], LPDDR4[6C], rk3588[1A], rk3588_LPDDR4[3C]), Port (bidir, see LPDDR4[1B], LPDDR4[6B], rk3588[1A], rk3588_LPDDR4[3C]), Port (bidir, see LPDDR4[1B], LPDDR4[6C], rk3588[1A], rk3588_LPDDR4[3C]), Port (bidir, see LPDDR4[6B], LPDDR4[6C], rk3588[1A], rk3588_LPDDR4[3C])

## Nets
DDR_CH0_A0_A: U?#2.T7(DDR_CH0_A0_A) U?#3.T7(DDR_CH0_A0_A) ; port DDR_CH0_A0_A
DDR_CH0_A0_B: U?#2.M8(DDR_CH0_A0_B) U?#3.M8(DDR_CH0_A0_B) ; port DDR_CH0_A0_B
DDR_CH0_A1_A: U?#2.T8(DDR_CH0_A1_A) U?#3.T8(DDR_CH0_A1_A) ; port DDR_CH0_A1_A
DDR_CH0_A1_B: U?#2.M5(DDR_CH0_A1_B) U?#3.M5(DDR_CH0_A1_B) ; port DDR_CH0_A1_B
DDR_CH0_A2_A: U?#2.P4(DDR_CH0_A2_A) U?#3.P4(DDR_CH0_A2_A) ; port DDR_CH0_A2_A
DDR_CH0_A2_B: U?#2.N5(DDR_CH0_A2_B) U?#3.N5(DDR_CH0_A2_B) ; port DDR_CH0_A2_B
DDR_CH0_A3_A: U?#2.P5(DDR_CH0_A3_A) U?#3.P5(DDR_CH0_A3_A) ; port DDR_CH0_A3_A
DDR_CH0_A3_B: U?#2.N4(DDR_CH0_A3_B) U?#3.N4(DDR_CH0_A3_B) ; port DDR_CH0_A3_B
DDR_CH0_A4_A: U?#2.R1(DDR_CH0_A4_A) U?#3.R1(DDR_CH0_A4_A) ; port DDR_CH0_A4_A
DDR_CH0_A4_B: U?#2.K1(DDR_CH0_A4_B) U?#3.K1(DDR_CH0_A4_B) ; port DDR_CH0_A4_B
DDR_CH0_A5_A: U?#2.P2(DDR_CH0_A5_A) U?#3.P2(DDR_CH0_A5_A) ; port DDR_CH0_A5_A
DDR_CH0_A5_B: U?#2.L2(DDR_CH0_A5_B) U?#3.L2(DDR_CH0_A5_B) ; port DDR_CH0_A5_B
DDR_CH0_A6_A: U?#2.T5(DDR_CH0_A6_A) U?#3.T5(DDR_CH0_A6_A) ; port DDR_CH0_A6_A
DDR_CH0_CLKN_A: U?#2.N1(DDR_CH0_CKB_A) U?#3.N1(DDR_CH0_CKB_A) ; port DDR_CH0_CLKN_A
DDR_CH0_CLKN_B: U?#2.M1(DDR_CH0_CKB_B) U?#3.M1(DDR_CH0_CKB_B) ; port DDR_CH0_CLKN_B
DDR_CH0_CLKP_A: U?#2.N2(DDR_CH0_CK_A) U?#3.N2(DDR_CH0_CK_A) ; port DDR_CH0_CLKP_A
DDR_CH0_CLKP_B: U?#2.M2(DDR_CH0_CK_B) U?#3.M2(DDR_CH0_CK_B) ; port DDR_CH0_CLKP_B
DDR_CH0_DM0_A: U?#2.Y4(DDR_CH0_DM0_A) U?#3.Y4(DDR_CH0_DM0_A) ; port DDR_CH0_DM0_A
DDR_CH0_DM0_B: U?#2.G4(DDR_CH0_DM0_B) U?#3.G4(DDR_CH0_DM0_B) ; port DDR_CH0_DM0_B
DDR_CH0_DM1_A: U?#2.AB4(DDR_CH0_DM1_A) U?#3.AB4(DDR_CH0_DM1_A) ; port DDR_CH0_DM1_A
DDR_CH0_DM1_B: U?#2.E4(DDR_CH0_DM1_B) U?#3.E4(DDR_CH0_DM1_B) ; port DDR_CH0_DM1_B
DDR_CH0_DQ0_A: U?#1.B2(DQ0_A) U?#2.U1(DDR_CH0_DQ0_A) U?#3.U1(DDR_CH0_DQ0_A) U?#4.B2(DQ0_A) ; port DDR_CH0_DQ0_A
DDR_CH0_DQ0_B: U?#1.AA2(DQ0_B) U?#1.J4(CKE0_A) U?#2.H1(DDR_CH0_DQ0_B) U?#3.H1(DDR_CH0_DQ0_B) U?#4.AA2(DQ0_B) ; port DDR_CH0_DQ0_B
DDR_CH0_DQ0N_B: U?#1.V3(DQS0_c_B) U?#2.J7(DDR_CH0_DQS0N_B) U?#3.J7(DDR_CH0_DQS0N_B) U?#4.V3(DQS0_c_B) ; port DDR_CH0_DQ0N_B
DDR_CH0_DQ1_A: U?#1.C2(DQ1_A) U?#2.T2(DDR_CH0_DQ1_A) U?#3.T2(DDR_CH0_DQ1_A) U?#4.C2(DQ1_A) ; port DDR_CH0_DQ1_A
DDR_CH0_DQ1_B: U?#1.P4(CKE0_B) U?#1.Y2(DQ1_B) U?#2.J2(DDR_CH0_DQ1_B) U?#3.J2(DDR_CH0_DQ1_B) U?#4.Y2(DQ1_B) ; port DDR_CH0_DQ1_B
DDR_CH0_DQ2_A: U?#1.E2(DQ2_A) U?#2.T1(DDR_CH0_DQ2_A) U?#3.T1(DDR_CH0_DQ2_A) U?#4.E2(DQ2_A) ; port DDR_CH0_DQ2_A
DDR_CH0_DQ2_B: U?#1.J5(CKE1_A) U?#1.V2(DQ2_B) U?#2.J1(DDR_CH0_DQ2_B) U?#3.J1(DDR_CH0_DQ2_B) U?#4.V2(DQ2_B) ; port DDR_CH0_DQ2_B
DDR_CH0_DQ3_A: U?#1.F2(DQ3_A) U?#2.R2(DDR_CH0_DQ3_A) U?#3.R2(DDR_CH0_DQ3_A) U?#4.F2(DQ3_A) ; port DDR_CH0_DQ3_A
DDR_CH0_DQ3_B: U?#1.P5(CKE1_B) U?#1.U2(DQ3_B) U?#2.K2(DDR_CH0_DQ3_B) U?#3.K2(DDR_CH0_DQ3_B) U?#4.U2(DQ3_B) ; port DDR_CH0_DQ3_B
DDR_CH0_DQ4_A: U?#1.F4(DQ4_A) U?#2.W1(DDR_CH0_DQ4_A) U?#3.W1(DDR_CH0_DQ4_A) U?#4.F4(DQ4_A) ; port DDR_CH0_DQ4_A
DDR_CH0_DQ4_B: U?#1.J9(CK_c_A) U?#1.U4(DQ4_B) U?#2.F1(DDR_CH0_DQ4_B) U?#3.F1(DDR_CH0_DQ4_B) U?#4.U4(DQ4_B) ; port DDR_CH0_DQ4_B
DDR_CH0_DQ5_A: U?#1.E4(DQ5_A) U?#2.V2(DDR_CH0_DQ5_A) U?#3.V2(DDR_CH0_DQ5_A) U?#4.E4(DQ5_A) ; port DDR_CH0_DQ5_A
DDR_CH0_DQ5_B: U?#1.P9(CK_c_B) U?#1.V4(DQ5_B) U?#2.G2(DDR_CH0_DQ5_B) U?#3.G2(DDR_CH0_DQ5_B) U?#4.V4(DQ5_B) ; port DDR_CH0_DQ5_B
DDR_CH0_DQ6_A: U?#1.C4(DQ6_A) U?#2.V1(DDR_CH0_DQ6_A) U?#3.V1(DDR_CH0_DQ6_A) U?#4.C4(DQ6_A) ; port DDR_CH0_DQ6_A
DDR_CH0_DQ6_B: U?#1.J8(CK_t_A) U?#1.Y4(DQ6_B) U?#2.G1(DDR_CH0_DQ6_B) U?#3.G1(DDR_CH0_DQ6_B) U?#4.Y4(DQ6_B) ; port DDR_CH0_DQ6_B
DDR_CH0_DQ7_A: U?#1.B4(DQ7_A) U?#2.U2(DDR_CH0_DQ7_A) U?#3.U2(DDR_CH0_DQ7_A) U?#4.B4(DQ7_A) ; port DDR_CH0_DQ7_A
DDR_CH0_DQ7_B: U?#1.AA4(DQ7_B) U?#1.P8(CK_t_B) U?#2.H2(DDR_CH0_DQ7_B) U?#3.H2(DDR_CH0_DQ7_B) U?#4.AA4(DQ7_B) ; port DDR_CH0_DQ7_B
DDR_CH0_DQ8_A: U?#1.B11(DQ8_A) U?#2.AB2(DDR_CH0_DQ8_A) U?#3.AB2(DDR_CH0_DQ8_A) U?#4.B11(DQ8_A) ; port DDR_CH0_DQ8_A
DDR_CH0_DQ8_B: U?#1.AA11(DQ8_B) U?#2.D2(DDR_CH0_DQ8_B) U?#3.D2(DDR_CH0_DQ8_B) U?#4.AA11(DQ8_B) ; port DDR_CH0_DQ8_B
DDR_CH0_DQ9_A: U?#1.C11(DQ9_A) U?#2.AB1(DDR_CH0_DQ9_A) U?#3.AB1(DDR_CH0_DQ9_A) U?#4.C11(DQ9_A) ; port DDR_CH0_DQ9_A
DDR_CH0_DQ9_B: U?#1.Y11(DQ9_B) U?#2.C1(DDR_CH0_DQ9_B) U?#3.C1(DDR_CH0_DQ9_B) U?#4.Y11(DQ9_B) ; port DDR_CH0_DQ9_B
DDR_CH0_DQ10_A: U?#1.E11(DQ10_A) U?#2.AC1(DDR_CH0_DQ10_A) U?#3.AC1(DDR_CH0_DQ10_A) U?#4.E11(DQ10_A) ; port DDR_CH0_DQ10_A
DDR_CH0_DQ10_B: U?#1.V11(DQ10_B) U?#2.C2(DDR_CH0_DQ10_B) U?#3.C2(DDR_CH0_DQ10_B) U?#4.V11(DQ10_B) ; port DDR_CH0_DQ10_B
DDR_CH0_DQ11_A: U?#1.F11(DQ11_A) U?#2.AC2(DDR_CH0_DQ11_A) U?#3.AC2(DDR_CH0_DQ11_A) U?#4.F11(DQ11_A) ; port DDR_CH0_DQ11_A
DDR_CH0_DQ11_B: U?#1.U11(DQ11_B) U?#2.B1(DDR_CH0_DQ11_B) U?#3.B1(DDR_CH0_DQ11_B) U?#4.U11(DQ11_B) ; port DDR_CH0_DQ11_B
DDR_CH0_DQ12_A: U?#1.F9(DQ12_A) U?#2.Y1(DDR_CH0_DQ12_A) U?#3.Y1(DDR_CH0_DQ12_A) U?#4.F9(DQ12_A) ; port DDR_CH0_DQ12_A
DDR_CH0_DQ12_B: U?#1.U9(DQ12_B) U?#2.F2(DDR_CH0_DQ12_B) U?#3.F2(DDR_CH0_DQ12_B) U?#4.U9(DQ12_B) ; port DDR_CH0_DQ12_B
DDR_CH0_DQ13_A: U?#1.E9(DQ13_A) U?#2.Y2(DDR_CH0_DQ13_A) U?#3.Y2(DDR_CH0_DQ13_A) U?#4.E9(DQ13_A) ; port DDR_CH0_DQ13_A
DDR_CH0_DQ13_B: U?#1.V9(DQ13_B) U?#2.E1(DDR_CH0_DQ13_B) U?#3.E1(DDR_CH0_DQ13_B) U?#4.V9(DQ13_B) ; port DDR_CH0_DQ13_B
DDR_CH0_DQ14_A: U?#1.C9(DQ14_A) U?#2.AA1(DDR_CH0_DQ14_A) U?#3.AA1(DDR_CH0_DQ14_A) U?#4.C9(DQ14_A) ; port DDR_CH0_DQ14_A
DDR_CH0_DQ14_B: U?#1.Y9(DQ14_B) U?#2.E2(DDR_CH0_DQ14_B) U?#3.E2(DDR_CH0_DQ14_B) U?#4.Y9(DQ14_B) ; port DDR_CH0_DQ14_B
DDR_CH0_DQ15_A: U?#1.B9(DQ15_A) U?#2.AA2(DDR_CH0_DQ15_A) U?#3.AA2(DDR_CH0_DQ15_A) U?#4.B9(DQ15_A) ; port DDR_CH0_DQ15_A
DDR_CH0_DQ15_B: U?#1.AA9(DQ15_B) U?#2.D1(DDR_CH0_DQ15_B) U?#3.D1(DDR_CH0_DQ15_B) U?#4.AA9(DQ15_B) ; port DDR_CH0_DQ15_B
DDR_CH0_DQS0N_A: U?#1.E3(DQS0_c_A) U?#2.U4(DDR_CH0_DQS0N_A) U?#3.U4(DDR_CH0_DQS0N_A) U?#4.E3(DQS0_c_A) ; port DDR_CH0_DQS0N_A
DDR_CH0_DQS0P_A: U?#1.D3(DQS0_t_A) U?#2.U5(DDR_CH0_DQS0P_A) U?#3.U5(DDR_CH0_DQS0P_A) U?#4.D3(DQS0_t_A) ; port DDR_CH0_DQS0P_A
DDR_CH0_DQS0P_B: U?#1.W3(DQS0_t_B) U?#2.J8(DDR_CH0_DQS0P_B) U?#3.J8(DDR_CH0_DQS0P_B) U?#4.W3(DQS0_t_B) ; port DDR_CH0_DQS0P_B
DDR_CH0_DQS1N_A: U?#1.E10(DQS1_c_A) U?#2.AA4(DDR_CH0_DQS1N_A) U?#3.AA4(DDR_CH0_DQS1N_A) U?#4.E10(DQS1_c_A) ; port DDR_CH0_DQS1N_A
DDR_CH0_DQS1N_B: U?#1.V10(DQS1_c_B) U?#2.F4(DDR_CH0_DQS1N_B) U?#3.F4(DDR_CH0_DQS1N_B) U?#4.V10(DQS1_c_B) ; port DDR_CH0_DQS1N_B
DDR_CH0_DQS1P_A: U?#1.D10(DQS1_t_A) U?#2.AA5(DDR_CH0_DQS1P_A) U?#3.AA5(DDR_CH0_DQS1P_A) U?#4.D10(DQS1_t_A) ; port DDR_CH0_DQS1P_A
DDR_CH0_DQS1P_B: U?#1.W10(DQS1_t_B) U?#2.F5(DDR_CH0_DQS1P_B) U?#3.F5(DDR_CH0_DQS1P_B) U?#4.W10(DQS1_t_B) ; port DDR_CH0_DQS1P_B
DDR_CH0_LP4/4X_CKE0/LP5_CS0_B: U?#2.L5(DDR_CH0_LP4/4X_CKE0/LP5_CS0_B) U?#3.L5(DDR_CH0_LP4/4X_CKE0/LP5_CS0_B) ; port DDR_CH0_LP4/4X_CKE0/LP5_CS0_B
DDR_CH0_LP4/4X_CKE0/LP5_CS1_B: U?#2.L4(DDR_CH0_LP4/4X_CKE1/LP5_CS1_B) U?#3.L4(DDR_CH0_LP4/4X_CKE1/LP5_CS1_B) ; port DDR_CH0_LP4/4X_CKE0/LP5_CS1_B
DDR_CH0_LP4/4X_CKE1/LP5_CS0_A: U?#2.P7(DDR_CH0_LP4/4X_CKE0/LP5_CS0_A) U?#3.P7(DDR_CH0_LP4/4X_CKE0/LP5_CS0_A) ; port DDR_CH0_LP4/4X_CKE1/LP5_CS0_A
DDR_CH0_LP4/4X_CKE1/LP5_CS1_A: U?#2.N7(DDR_CH0_LP4/4X_CKE1/LP5_CS1_A) U?#3.N7(DDR_CH0_LP4/4X_CKE1/LP5_CS1_A) ; port DDR_CH0_LP4/4X_CKE1/LP5_CS1_A
DDR_CH0_LP4/4X_CS0_A: U?#2.R6(DDR_CH0_LP4/4X_CS0_A) U?#3.R6(DDR_CH0_LP4/4X_CS0_A) ; port DDR_CH0_LP4/4X_CS0_A
DDR_CH0_LP4/4X_CS0_B: U?#2.L7(DDR_CH0_LP4/4X_CS0_B) U?#3.L7(DDR_CH0_LP4/4X_CS0_B) ; port DDR_CH0_LP4/4X_CS0_B
DDR_CH0_LP4/4X_CS1_A: U?#2.R7(DDR_CH0_LP4/4X_CS1_A) U?#3.R7(DDR_CH0_LP4/4X_CS1_A) ; port DDR_CH0_LP4/4X_CS1_A
DDR_CH0_LP4/4X_CS1_B: U?#2.L8(DDR_CH0_LP4/4X_CS1_B) U?#3.L8(DDR_CH0_LP4/4X_CS1_B) ; port DDR_CH0_LP4/4X_CS1_B
Port: U?#2.H7(DDR_CH0_ZQ_B) U?#3.H7(DDR_CH0_ZQ_B) ; port Port

Not connected (* = marked no-connect by the designer): U?#1 A1(DNU) A2(DNU) A3(VSS) A4(VDD2) A5(ZQ0) A8(ZQ1) A9(VDD2) A10(VSS) A11(DNU) A12(DNU) AA1(DNU) AA3(VDDQ) AA5(VDDQ) AA8(VDDQ) AA10(VDDQ) AA12(DNU) AB1(DNU) AB2(DNU) AB3(VSS) AB4(VDD2) AB5(VSS) AB8(VSS) AB9(VDD2) AB10(VSS) AB11(DNU) AB12(DNU) B1(DNU) B3(VDDQ) B5(VDDQ) B8(VDDQ) B10(VDDQ) B12(DNU) C1(VSS) C3(DMI0_A) C5(VSS) C8(VSS) C10(DMI1_A) C12(VSS) D1(VDDQ) D2(VSS) D4(VSS) D5(VDDQ) D8(VDDQ) D9(VSS) D11(VSS) D12(VDDQ) E1(VSS) E5(VSS) E8(VSS) E12(VSS) F1(VDD1) F3(VDDQ) F5(VDD2) F8(VDD2) F10(VDDQ) F12(VDD1) G1(VSS) G2(ODT_CA_A) G3(VSS) G4(VDD1) G5(VSS) G8(VSS) G9(VDD1) G10(VSS) G11(NC) G12(VSS) H1(VDD2) H2(CA0_A) H3(CS1_A) H4(CS0_A) H5(VDD2) H8(VDD2) H9(CA2_A) H10(CA3_A) H11(CA4_A) H12(VDD2) J1(VSS) J2(CA1_A) J3(VSS) J10(VSS) J11(CA5_A) J12(VSS) K1(VDD2) K2(VSS) K3(VDD2) K4(VSS) K5(NC) K8(NC) K9(VSS) K10(VDD2) K11(VSS) K12(VDD2) N1(VDD2) N2(VSS) N3(VDD2) N4(VSS) N5(NC) N8(NC) N9(VSS) N10(VDD2) N11(VSS) N12(VDD2) P1(VSS) P2(CA1_B) P3(VSS) P10(VSS) P11(CA5_B) P12(VSS) R1(VDD2) R2(CA0_B) R3(CS1_B) R4(CS0_B) R5(VDD2) R8(VDD2) R9(CA2_B) R10(CA3_B) R11(CA4_B) R12(VDD2) T1(VSS) T2(ODT_CA_B) T3(VSS) T4(VDD1) T5(VSS) T8(VSS) T9(VDD1) T10(VSS) T11(RESET_n) T12(VSS) U1(VDD1) U3(VDDQ) U5(VDD2) U8(VDD2) U10(VDDQ) U12(VDD1) V1(VSS) V5(VSS) V8(VSS) V12(VSS) W1(VDDQ) W2(VSS) W4(VSS) W5(VDDQ) W8(VDDQ) W9(VSS) W11(VSS) W12(VDDQ) Y1(VSS) Y3(DMI0_B) Y5(VSS) Y8(VSS) Y10(DMI1_B) Y12(VSS); U?#2 H4(DDR_CH0_WCK1P_B) H5(DDR_CH0_WCK1N_B) K4(DDR_CH0_WCK0N_B) K5(DDR_CH0_WCK0P_B) K7(DDR_CH0_RESET_B) L10(DDR_CH0_VDDQ_CK) M7(DDR_CH0_A6_B) M10(DDR_CH0_VDDQ_0) M11(DDR_CH0_PLL_AVSS) M12(DDR_CH0_PLL_AVDD1V8) N8(DDR_CH0_VDDQ_CKE) N10(DDR_CH0_VDDQ_1) N12(DDR_CH0_PLL_DVDD) N13(DDR_CH0_VDD_MIF_0) P10(DDR_CH0_VDDQ_2) P12(DDR_CH0_VDD_3) P13(DDR_CH0_VDD_MIF_1) R10(DDR_CH0_VDDQ_3) R12(DDR_CH0_VDD_2) T4(DDR_CH0_RESET_A) T10(DDR_CH0_VDDQ_4) T12(DDR_CH0_VDD_1) U11(DDR_CH0_VDD_0) V6(DDR_CH0_WCK0N_A) V7(DDR_CH0_WCK0P_A) W4(DDR_CH0_WCK1P_A) W5(DDR_CH0_WCK1N_A) W8(DDR_CH0_ZQ_A); U?#3 H4(DDR_CH0_WCK1P_B) H5(DDR_CH0_WCK1N_B) K4(DDR_CH0_WCK0N_B) K5(DDR_CH0_WCK0P_B) K7(DDR_CH0_RESET_B) L10(DDR_CH0_VDDQ_CK) M7(DDR_CH0_A6_B) M10(DDR_CH0_VDDQ_0) M11(DDR_CH0_PLL_AVSS) M12(DDR_CH0_PLL_AVDD1V8) N8(DDR_CH0_VDDQ_CKE) N10(DDR_CH0_VDDQ_1) N12(DDR_CH0_PLL_DVDD) N13(DDR_CH0_VDD_MIF_0) P10(DDR_CH0_VDDQ_2) P12(DDR_CH0_VDD_3) P13(DDR_CH0_VDD_MIF_1) R10(DDR_CH0_VDDQ_3) R12(DDR_CH0_VDD_2) T4(DDR_CH0_RESET_A) T10(DDR_CH0_VDDQ_4) T12(DDR_CH0_VDD_1) U11(DDR_CH0_VDD_0) V6(DDR_CH0_WCK0N_A) V7(DDR_CH0_WCK0P_A) W4(DDR_CH0_WCK1P_A) W5(DDR_CH0_WCK1N_A) W8(DDR_CH0_ZQ_A); U?#4 A1(DNU) A2(DNU) A3(VSS) A4(VDD2) A5(ZQ0) A8(ZQ1) A9(VDD2) A10(VSS) A11(DNU) A12(DNU) AA1(DNU) AA3(VDDQ) AA5(VDDQ) AA8(VDDQ) AA10(VDDQ) AA12(DNU) AB1(DNU) AB2(DNU) AB3(VSS) AB4(VDD2) AB5(VSS) AB8(VSS) AB9(VDD2) AB10(VSS) AB11(DNU) AB12(DNU) B1(DNU) B3(VDDQ) B5(VDDQ) B8(VDDQ) B10(VDDQ) B12(DNU) C1(VSS) C3(DMI0_A) C5(VSS) C8(VSS) C10(DMI1_A) C12(VSS) D1(VDDQ) D2(VSS) D4(VSS) D5(VDDQ) D8(VDDQ) D9(VSS) D11(VSS) D12(VDDQ) E1(VSS) E5(VSS) E8(VSS) E12(VSS) F1(VDD1) F3(VDDQ) F5(VDD2) F8(VDD2) F10(VDDQ) F12(VDD1) G1(VSS) G2(ODT_CA_A) G3(VSS) G4(VDD1) G5(VSS) G8(VSS) G9(VDD1) G10(VSS) G11(NC) G12(VSS) H1(VDD2) H2(CA0_A) H3(CS1_A) H4(CS0_A) H5(VDD2) H8(VDD2) H9(CA2_A) H10(CA3_A) H11(CA4_A) H12(VDD2) J1(VSS) J2(CA1_A) J3(VSS) J4(CKE0_A) J5(CKE1_A) J8(CK_t_A) J9(CK_c_A) J10(VSS) J11(CA5_A) J12(VSS) K1(VDD2) K2(VSS) K3(VDD2) K4(VSS) K5(NC) K8(NC) K9(VSS) K10(VDD2) K11(VSS) K12(VDD2) N1(VDD2) N2(VSS) N3(VDD2) N4(VSS) N5(NC) N8(NC) N9(VSS) N10(VDD2) N11(VSS) N12(VDD2) P1(VSS) P2(CA1_B) P3(VSS) P4(CKE0_B) P5(CKE1_B) P8(CK_t_B) P9(CK_c_B) P10(VSS) P11(CA5_B) P12(VSS) R1(VDD2) R2(CA0_B) R3(CS1_B) R4(CS0_B) R5(VDD2) R8(VDD2) R9(CA2_B) R10(CA3_B) R11(CA4_B) R12(VDD2) T1(VSS) T2(ODT_CA_B) T3(VSS) T4(VDD1) T5(VSS) T8(VSS) T9(VDD1) T10(VSS) T11(RESET_n) T12(VSS) U1(VDD1) U3(VDDQ) U5(VDD2) U8(VDD2) U10(VDDQ) U12(VDD1) V1(VSS) V5(VSS) V8(VSS) V12(VSS) W1(VDDQ) W2(VSS) W4(VSS) W5(VDDQ) W8(VDDQ) W9(VSS) W11(VSS) W12(VDDQ) Y1(VSS) Y3(DMI0_B) Y5(VSS) Y8(VSS) Y10(DMI1_B) Y12(VSS)

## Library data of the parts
U?#1 U?#4 = FLXC2004G-N1
U?#2 U?#3 = RK3588: low power, high performance processor; MF: Fuzhou Rockchip Electronics Co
